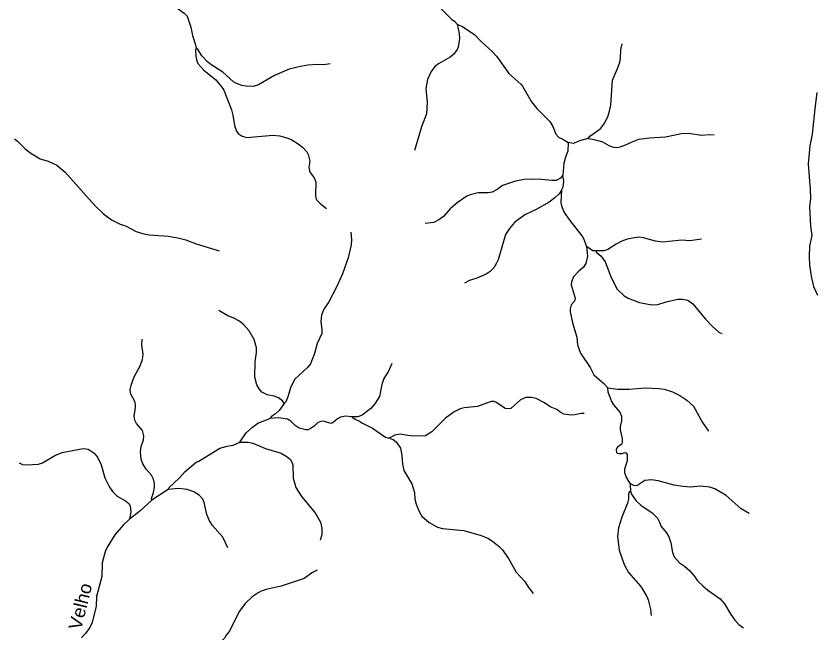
# Model space of a CAD drawing. Extents: x 320.3 to 346.3, y 7455.4 to 7483.3.
# Drawn here: x 331.104 to 335.986, y 7457.669 to 7461.432 of the extents above; entities that cross this region are included whole.
import ezdxf
from ezdxf.enums import TextEntityAlignment as Align

# ---------------------------------------------------------------- set-up
doc = ezdxf.new("R2010")
doc.units = 0
doc.header["$LTSCALE"] = 0.032
doc.layers.add('61', color=7, linetype='Continuous')
doc.layers.add('7', color=7, linetype='Continuous', lineweight=25)

msp = doc.modelspace()

# ---------------------------------------------------------------- linework, layer by layer
at = {"layer": '7'}
msp.add_line((332.0325, 7458.5442), (331.9329, 7458.4789), dxfattribs=at)
for points in [[(331.6885, 7461.7612), (331.6915, 7461.7515), (331.7137, 7461.738), (331.7672, 7461.7264), (331.8244, 7461.6949), (331.8472, 7461.6883), (331.8985, 7461.6812), (331.922, 7461.6723), (331.9413, 7461.6589), (331.9753, 7461.628), (332.0109, 7461.5874), (332.0609, 7461.5093), (332.0936, 7461.4761), (332.1307, 7461.4507), (332.1493, 7461.4317), (332.1714, 7461.3653), (332.1815, 7461.313), (332.2005, 7461.2565), (332.204, 7461.2362)], [(333.68, 7461.5031), (333.6857, 7461.491), (333.7066, 7461.4688), (333.7648, 7461.4117), (333.7802, 7461.4004), (333.7958, 7461.3825)], [(333.7958, 7461.3825), (333.8078, 7461.3258), (333.8103, 7461.295), (333.8019, 7461.2421), (333.7971, 7461.2284), (333.7765, 7461.1993), (333.7543, 7461.1804), (333.6833, 7461.1416), (333.661, 7461.1235), (333.6383, 7461.0938), (333.6145, 7461.0442), (333.6046, 7460.9901), (333.6125, 7460.9059), (333.6102, 7460.8351), (333.5795, 7460.7556), (333.537, 7460.6114)], [(333.7958, 7461.3825), (333.8315, 7461.366), (333.9017, 7461.3199), (333.943, 7461.2761), (334.0107, 7461.2168), (334.0371, 7461.1876), (334.1113, 7461.0826), (334.186, 7461.0174), (334.1958, 7461.0055), (334.2504, 7460.9099), (334.2823, 7460.8677), (334.3619, 7460.7887), (334.3798, 7460.7585), (334.3991, 7460.7123), (334.4157, 7460.6941), (334.4414, 7460.682), (334.4743, 7460.6601)], [(332.204, 7461.2362), (332.1988, 7461.2244), (332.2013, 7461.1916), (332.2055, 7461.1645), (332.2146, 7461.1437), (332.2506, 7461.1014), (332.3227, 7461.0422), (332.3656, 7460.9907), (332.3718, 7460.9795), (332.4194, 7460.861), (332.4277, 7460.8285), (332.4375, 7460.7636), (332.4508, 7460.7299), (332.4608, 7460.7155), (332.4851, 7460.6991), (332.5121, 7460.6921), (332.6723, 7460.7055), (332.7147, 7460.7016), (332.7627, 7460.687), (332.7866, 7460.6762), (332.8267, 7460.652), (332.8528, 7460.6321), (332.8787, 7460.6048), (332.8875, 7460.5881), (332.8968, 7460.5462), (332.8922, 7460.5095), (332.8956, 7460.4889), (332.9, 7460.4785), (332.9237, 7460.4462), (332.9348, 7460.4218), (332.9319, 7460.3402), (332.9349, 7460.3217), (332.9408, 7460.3092), (332.9603, 7460.2895), (332.9988, 7460.259)], [(333.0213, 7461.1399), (332.9827, 7461.1351), (332.9431, 7461.1367), (332.8846, 7461.132), (332.8402, 7461.1251), (332.7721, 7461.109), (332.6809, 7461.0694), (332.5843, 7461.0122), (332.5505, 7461.0033), (332.5091, 7461.0038), (332.4828, 7461.0079), (332.4448, 7461.0224), (332.4316, 7461.0305), (332.3669, 7461.0892), (332.2931, 7461.1365), (332.273, 7461.1527), (332.2376, 7461.1888), (332.2151, 7461.2252), (332.204, 7461.2362)], [(334.5953, 7460.6843), (334.6067, 7460.7005), (334.6619, 7460.7378), (334.6727, 7460.7487), (334.6972, 7460.7812), (334.7173, 7460.8229), (334.7268, 7460.8519), (334.7341, 7460.8892), (334.7437, 7461.0414), (334.7753, 7461.1118), (334.7886, 7461.1496), (334.7932, 7461.1763), (334.7944, 7461.2278), (334.8033, 7461.263)], [(335.9923, 7460.9668), (335.9784, 7460.8664), (335.9636, 7460.711), (335.9487, 7460.6401), (335.938, 7460.5277), (335.9511, 7460.3733), (335.952, 7460.3187), (335.9474, 7460.2675), (335.9535, 7460.1506), (335.9601, 7460.0941), (335.9472, 7460.0285), (335.9441, 7459.9655), (335.9459, 7459.9124), (335.957, 7459.8464), (335.9703, 7459.7827), (335.9955, 7459.7294)], [(334.5953, 7460.6843), (334.6226, 7460.6818), (334.6629, 7460.6715), (334.6825, 7460.6641), (334.7261, 7460.6402), (334.7514, 7460.6321), (334.7727, 7460.6303), (334.7912, 7460.6335), (334.8195, 7460.6442), (334.8642, 7460.6658), (334.9051, 7460.681), (334.9705, 7460.6895), (335.0687, 7460.6959), (335.1649, 7460.7152), (335.2061, 7460.7175), (335.2894, 7460.7065), (335.3364, 7460.7102), (335.3641, 7460.7071)], [(331.0942, 7460.6831), (331.1135, 7460.6696), (331.1602, 7460.6219), (331.1939, 7460.5955), (331.2523, 7460.5621), (331.3006, 7460.5472), (331.3542, 7460.5225), (331.4042, 7460.4798), (331.5837, 7460.2776), (331.638, 7460.2265), (331.6875, 7460.189), (331.74, 7460.1632), (331.7728, 7460.1515), (331.8368, 7460.1189), (331.8758, 7460.1054), (331.9161, 7460.0975), (332.0326, 7460.09), (332.091, 7460.0802), (332.14, 7460.0661), (332.2036, 7460.0419), (332.3439, 7459.9999)], [(334.4743, 7460.6601), (334.472, 7460.6081), (334.4595, 7460.5775), (334.4471, 7460.5346), (334.4418, 7460.4609)], [(334.5953, 7460.6843), (334.5426, 7460.6701), (334.506, 7460.6551), (334.4743, 7460.6601)], [(334.4418, 7460.4609), (334.4267, 7460.4429), (334.3998, 7460.4297), (334.3748, 7460.4288), (334.3114, 7460.435), (334.2505, 7460.4368), (334.2063, 7460.4352), (334.1526, 7460.4258), (334.0734, 7460.3977), (334.0405, 7460.3734), (334.0094, 7460.357), (333.9859, 7460.3528), (333.9247, 7460.3535), (333.8767, 7460.3421), (333.8562, 7460.3337), (333.797, 7460.2923), (333.7542, 7460.2559), (333.7124, 7460.2098), (333.6845, 7460.1897), (333.6533, 7460.1735), (333.6021, 7460.1665)], [(334.4341, 7460.3691), (334.4431, 7460.3894), (334.4479, 7460.4252), (334.4418, 7460.4609)], [(334.4341, 7460.3691), (334.4181, 7460.3468), (334.3928, 7460.3225), (334.3582, 7460.296), (334.2784, 7460.2519), (334.2101, 7460.2194), (334.1462, 7460.1728), (334.115, 7460.1372), (334.0923, 7460.0997), (334.0462, 7459.9451), (334.0373, 7459.9247), (334.0194, 7459.8964), (333.9978, 7459.8744), (333.9725, 7459.8573), (333.917, 7459.8328), (333.872, 7459.8185), (333.8403, 7459.802)], [(334.4341, 7460.3691), (334.4289, 7460.2939), (334.4329, 7460.2735), (334.4505, 7460.2331), (334.4842, 7460.1848), (334.557, 7460.0914), (334.5667, 7460.0756), (334.586, 7460.0257)], [(333.1476, 7460.1142), (333.1506, 7460.0671), (333.1489, 7460.036), (333.131, 7459.9566), (333.0974, 7459.8603), (333.0602, 7459.7779), (333.0128, 7459.6894), (332.9835, 7459.6432), (332.968, 7459.6084), (332.9641, 7459.5692), (332.9713, 7459.5179), (332.9711, 7459.4953), (332.9429, 7459.4355), (332.9242, 7459.3685), (332.9085, 7459.3264), (332.9007, 7459.3101), (332.8836, 7459.2874), (332.8046, 7459.2151), (332.7784, 7459.1637), (332.7632, 7459.1093), (332.7508, 7459.078), (332.7409, 7459.0682)], [(335.2868, 7460.0715), (335.216, 7460.0618), (335.1674, 7460.0646), (335.0882, 7460.056), (335.0486, 7460.0522), (335.0071, 7460.058), (334.9335, 7460.0798), (334.907, 7460.083), (334.8913, 7460.0817), (334.833, 7460.0718), (334.8008, 7460.0598), (334.7663, 7460.0414), (334.7156, 7460.0075), (334.6915, 7460.0006), (334.6458, 7459.9996)], [(334.586, 7460.0257), (334.5924, 7459.9679), (334.5812, 7459.9231), (334.5673, 7459.9005), (334.5369, 7459.8735), (334.5064, 7459.8405), (334.4937, 7459.8116), (334.4925, 7459.7933), (334.5168, 7459.7104), (334.5119, 7459.6934), (334.4916, 7459.6706), (334.4866, 7459.6461), (334.4866, 7459.628), (334.4994, 7459.5606), (334.5258, 7459.4732), (334.53, 7459.4274), (334.5492, 7459.3753), (334.6077, 7459.289), (334.6312, 7459.2434), (334.6921, 7459.1898), (334.7156, 7459.1633)], [(334.6458, 7459.9996), (334.6235, 7460), (334.586, 7460.0257)], [(334.6458, 7459.9996), (334.6455, 7459.9922), (334.6737, 7459.9686), (334.6998, 7459.9332), (334.7367, 7459.8379), (334.7722, 7459.7663), (334.8154, 7459.726), (334.8403, 7459.7113), (334.9084, 7459.685), (334.9846, 7459.6712), (335.0204, 7459.6729), (335.0711, 7459.6885), (335.1422, 7459.7045), (335.1722, 7459.706), (335.204, 7459.6984), (335.2352, 7459.6765), (335.3124, 7459.5832), (335.3544, 7459.5383), (335.3925, 7459.5048), (335.4107, 7459.4955)], [(332.7409, 7459.0682), (332.73, 7459.0853), (332.706, 7459.1025), (332.6793, 7459.1127), (332.6366, 7459.1222), (332.6051, 7459.1368), (332.5881, 7459.1572), (332.5734, 7459.1826), (332.5618, 7459.2289), (332.5639, 7459.3228), (332.572, 7459.379), (332.5726, 7459.4092), (332.5573, 7459.4593), (332.528, 7459.5113), (332.4954, 7459.5476), (332.4673, 7459.5709), (332.4295, 7459.592), (332.3974, 7459.6042), (332.3423, 7459.6363)], [(331.9329, 7458.4789), (331.9306, 7458.489), (331.9437, 7458.5265), (331.9484, 7458.5584), (331.9484, 7458.5815), (331.9436, 7458.607), (331.9308, 7458.6309), (331.8991, 7458.6682), (331.8781, 7458.7011), (331.8671, 7458.7284), (331.864, 7458.7725), (331.8688, 7458.8064), (331.8832, 7458.8477), (331.8837, 7458.8724), (331.8753, 7458.9031), (331.8397, 7458.9471), (331.8292, 7458.9678), (331.8258, 7458.9921), (331.8343, 7459.0448), (331.8335, 7459.0633), (331.8287, 7459.0802), (331.8055, 7459.1254), (331.8016, 7459.1516), (331.8071, 7459.1807), (331.825, 7459.2319), (331.8624, 7459.2985), (331.876, 7459.3364), (331.8802, 7459.37), (331.8712, 7459.4239), (331.8732, 7459.4609)], [(333.3986, 7459.3129), (333.3774, 7459.2654), (333.3499, 7459.222), (333.3361, 7459.185), (333.3215, 7459.1122), (333.2939, 7459.0657), (333.2699, 7459.0373), (333.2158, 7458.9972), (333.1908, 7458.9881), (333.1535, 7458.9866)], [(334.7156, 7459.1633), (334.7756, 7459.1551), (334.845, 7459.1562), (334.9458, 7459.1638), (335.029, 7459.1606), (335.0607, 7459.1552), (335.1106, 7459.1407), (335.1555, 7459.1182), (335.1974, 7459.0889), (335.2382, 7459.0519), (335.2946, 7458.9534), (335.3303, 7458.8993)], [(334.8553, 7458.5785), (334.8296, 7458.6168), (334.8192, 7458.6465), (334.82, 7458.6694), (334.8359, 7458.7211), (334.835, 7458.7567), (334.8294, 7458.7648), (334.8217, 7458.7678), (334.7986, 7458.761), (334.7837, 7458.7608), (334.7732, 7458.7645), (334.7701, 7458.7702), (334.7697, 7458.788), (334.7733, 7458.7981), (334.7818, 7458.8086), (334.8025, 7458.8246), (334.8057, 7458.8333), (334.8056, 7458.8555), (334.7929, 7458.9074), (334.7938, 7458.9293), (334.8021, 7458.962), (334.8024, 7458.9884), (334.7892, 7459.0181), (334.7536, 7459.0609), (334.7387, 7459.0852), (334.7178, 7459.1385), (334.7156, 7459.1633)], [(334.5708, 7459.0079), (334.5526, 7459.0079), (334.514, 7458.9995), (334.4922, 7458.9984), (334.447, 7459.0032), (334.4248, 7459.0156), (334.4049, 7459.033), (334.3642, 7459.0476), (334.3287, 7459.072), (334.2777, 7459.0985), (334.2503, 7459.1062), (334.2151, 7459.1046), (334.1835, 7459.092), (334.1237, 7459.0381), (334.1161, 7459.0356), (334.0889, 7459.0378), (334.0328, 7459.0761), (334.0224, 7459.0806), (334.0043, 7459.0815), (333.9204, 7459.051), (333.8383, 7459.042), (333.8155, 7459.0354), (333.7788, 7459.0185), (333.7253, 7458.9791), (333.6414, 7458.8954), (333.6025, 7458.871), (333.534, 7458.869), (333.4955, 7458.8726), (333.4495, 7458.8815), (333.4157, 7458.8746), (333.3863, 7458.8584)], [(332.7409, 7459.0682), (332.7103, 7459.0254), (332.688, 7459.0058), (332.6629, 7458.9898), (332.6528, 7458.9771)], [(333.1535, 7458.9866), (333.114, 7458.9909), (333.0851, 7458.985), (333.0671, 7458.9749), (333.0381, 7458.95), (333.0263, 7458.9471), (332.9809, 7458.9606), (332.9648, 7458.9591), (332.945, 7458.9512), (332.9212, 7458.9282), (332.9024, 7458.9153), (332.8872, 7458.9089), (332.8727, 7458.9073), (332.8323, 7458.9181), (332.8077, 7458.9349), (332.781, 7458.9606), (332.7612, 7458.9721), (332.7066, 7458.9806), (332.6528, 7458.9771)], [(333.1535, 7458.9866), (333.1732, 7458.9733), (333.2049, 7458.9586), (333.2139, 7458.9501), (333.2801, 7458.9184), (333.3594, 7458.864), (333.3727, 7458.859), (333.3863, 7458.8584)], [(332.4697, 7458.8338), (332.5081, 7458.8894), (332.547, 7458.9251), (332.5797, 7458.9478), (332.6528, 7458.9771)], [(333.3863, 7458.8584), (333.3909, 7458.8538), (333.4065, 7458.85), (333.4241, 7458.8352), (333.45, 7458.7952), (333.4592, 7458.7518), (333.4619, 7458.6989), (333.4713, 7458.6608), (333.52, 7458.5783), (333.5361, 7458.5263), (333.5391, 7458.485), (333.5454, 7458.4549), (333.5639, 7458.41), (333.5804, 7458.3822), (333.6256, 7458.3419), (333.6764, 7458.314), (333.7072, 7458.3063), (333.8378, 7458.2935), (333.9428, 7458.2644), (333.9843, 7458.2462), (334.0124, 7458.2295), (334.0525, 7458.1965), (334.0706, 7458.1776), (334.1089, 7458.1232), (334.1561, 7458.0407), (334.2086, 7457.9822), (334.2272, 7457.9521), (334.2602, 7457.9098)], [(331.1242, 7458.7062), (331.1445, 7458.6972), (331.1678, 7458.6943), (331.2414, 7458.6989), (331.2653, 7458.7074), (331.3405, 7458.7511), (331.3862, 7458.7691), (331.5009, 7458.7925), (331.5159, 7458.7934), (331.5452, 7458.7892), (331.5817, 7458.7656), (331.6025, 7458.7411), (331.624, 7458.695), (331.6462, 7458.6145), (331.6742, 7458.5581), (331.6931, 7458.5309), (331.7219, 7458.5042), (331.7724, 7458.4756), (331.7931, 7458.4587), (331.8003, 7458.4446), (331.8046, 7458.4068), (331.7962, 7458.3639)], [(332.0325, 7458.5442), (332.0376, 7458.5543), (332.1023, 7458.6157), (332.137, 7458.6539), (332.2034, 7458.7104), (332.2196, 7458.7169), (332.3489, 7458.7961), (332.3919, 7458.8092), (332.4296, 7458.8153), (332.4697, 7458.8338)], [(332.4697, 7458.8338), (332.521, 7458.833), (332.5503, 7458.8269), (332.6273, 7458.7941), (332.7217, 7458.7647), (332.7526, 7458.7484), (332.7774, 7458.7288), (332.79, 7458.7075), (332.7943, 7458.6934), (332.7959, 7458.614), (332.8117, 7458.557), (332.8463, 7458.5021), (332.9301, 7458.4024), (332.9625, 7458.3441), (332.9707, 7458.3083), (332.9709, 7458.2681), (332.9609, 7458.234)], [(335.5781, 7458.3973), (335.5289, 7458.4265), (335.4373, 7458.5081), (335.3691, 7458.5487), (335.3379, 7458.5578), (335.2808, 7458.5654), (335.2212, 7458.5592), (335.1753, 7458.5619), (335.1205, 7458.57), (335.023, 7458.5964), (334.9815, 7458.6038), (334.9411, 7458.5983), (334.8937, 7458.5666), (334.8751, 7458.5683), (334.8553, 7458.5785)], [(332.3978, 7458.1881), (332.3655, 7458.2526), (332.3034, 7458.3248), (332.2846, 7458.3521), (332.2688, 7458.3913), (332.2532, 7458.4648), (332.2435, 7458.4844), (332.2229, 7458.5104), (332.1891, 7458.5289), (332.1481, 7458.5433), (332.0987, 7458.5496), (332.0325, 7458.5442)], [(334.8553, 7458.5785), (334.8519, 7458.5726), (334.8543, 7458.5345)], [(334.8543, 7458.5345), (334.8462, 7458.5272), (334.8419, 7458.5169), (334.8422, 7458.4842), (334.8366, 7458.4597), (334.8018, 7458.3759), (334.7807, 7458.3102), (334.7752, 7458.2572), (334.7843, 7458.1734), (334.8154, 7458.0863), (334.8423, 7458.0374), (334.917, 7457.9515), (334.9538, 7457.8908), (334.9623, 7457.8701), (334.9771, 7457.8141), (334.9803, 7457.7746)], [(334.8543, 7458.5345), (334.8603, 7458.5151), (334.887, 7458.4777), (334.9176, 7458.4491), (334.9866, 7458.4008), (335.0186, 7458.3695), (335.0322, 7458.3449), (335.0417, 7458.3191), (335.074, 7458.2799), (335.0891, 7458.2543), (335.1006, 7458.2186), (335.1108, 7458.1606), (335.1218, 7458.1332), (335.1525, 7458.0975), (335.1844, 7458.0759), (335.2143, 7458.0503), (335.2415, 7458.0199), (335.2638, 7457.9878), (335.2949, 7457.9559), (335.3261, 7457.9304), (335.4019, 7457.877), (335.4274, 7457.8461), (335.466, 7457.7814), (335.4913, 7457.7472), (335.5153, 7457.7209), (335.5443, 7457.7006)], [(331.9329, 7458.4789), (331.8595, 7458.4124), (331.7962, 7458.3639)], [(331.7962, 7458.3639), (331.7574, 7458.3264), (331.7079, 7458.2676), (331.6636, 7458.1988), (331.6509, 7458.1722), (331.6304, 7458.0959), (331.6283, 7458.0136), (331.5952, 7457.891), (331.5938, 7457.833), (331.5697, 7457.7318), (331.5537, 7457.7025), (331.5284, 7457.6666), (331.5084, 7457.6461), (331.5047, 7457.6368)], [(332.9424, 7458.0514), (332.9127, 7458.0375), (332.8636, 7458.0018), (332.7227, 7457.9545), (332.6316, 7457.9347), (332.6, 7457.9234), (332.5817, 7457.9134), (332.545, 7457.8886), (332.5046, 7457.8515), (332.4665, 7457.7996), (332.4065, 7457.6807), (332.3863, 7457.6546), (332.3766, 7457.6367), (332.2946, 7457.5617), (332.2704, 7457.5427), (332.223, 7457.5127), (332.1826, 7457.4959), (332.1268, 7457.4797), (332.0533, 7457.4765)]]:
    msp.add_lwpolyline(points, dxfattribs=at)

# ---------------------------------------------------------------- texts
at = {"layer": '61', "width": 1.05}
msp.add_text('Velho', height=0.08, rotation=76.068, dxfattribs=at).set_placement((331.5353, 7457.8212), align=Align.CENTER)

doc.saveas('drawing.dxf')
